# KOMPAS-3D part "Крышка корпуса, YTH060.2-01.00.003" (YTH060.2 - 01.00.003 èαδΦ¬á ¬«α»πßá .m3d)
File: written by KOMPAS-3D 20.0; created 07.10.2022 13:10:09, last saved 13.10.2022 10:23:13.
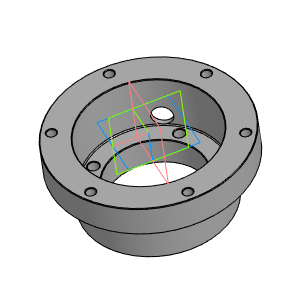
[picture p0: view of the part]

Document properties: Автор: Пользователь Windows; Полное имя файла: D:\информация пользователя\Desktop\ШОРОХ 2022\Насос ХИМия\YTH060.2 С торцевым уплотнением\3D  модель\YTH060.2 Насос сторцевым уплотнением\YTH060.2 - 01.00.003 Крышка корпуса .m3d

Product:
- Part/product: Крышка корпуса  | designation YTH060.2-01.00.003
    Материал: Полипропилен  ГОСТ 26996-86 (density 900 kg/m3)
    Масса: 0.255836
    signatures: Разработал Шорохов Д.А.; Проверил Гуляев А.С.; Утвердил Басалов И.С.

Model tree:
1. Операция без истории:1  (labels: 22-0602 Корпус. Вторая половина)
2. Фаска:1  (with: Операция без истории:1)
     Угол = 45; Длина 1 = 0.5; Длина 2 = 0.5
3. Фаска:2  (with: Операция без истории:1)
     Угол = 45; Длина 1 = 0.5; Длина 2 = 0.5
4. Эскиз:1  (with: Операция без истории:1)
5. Фаска:3  (with: Операция без истории:1)
     Угол = 45; Длина 1 = 0.5; Длина 2 = 0.5
6. Скругление:1  (with: Операция без истории:1)  (labels: Полипропилен  ГОСТ 26996-86)
     Радиус = 0.8

Expressions: 22-0602 Корпус. Вторая половина v1
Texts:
  YTH060.2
